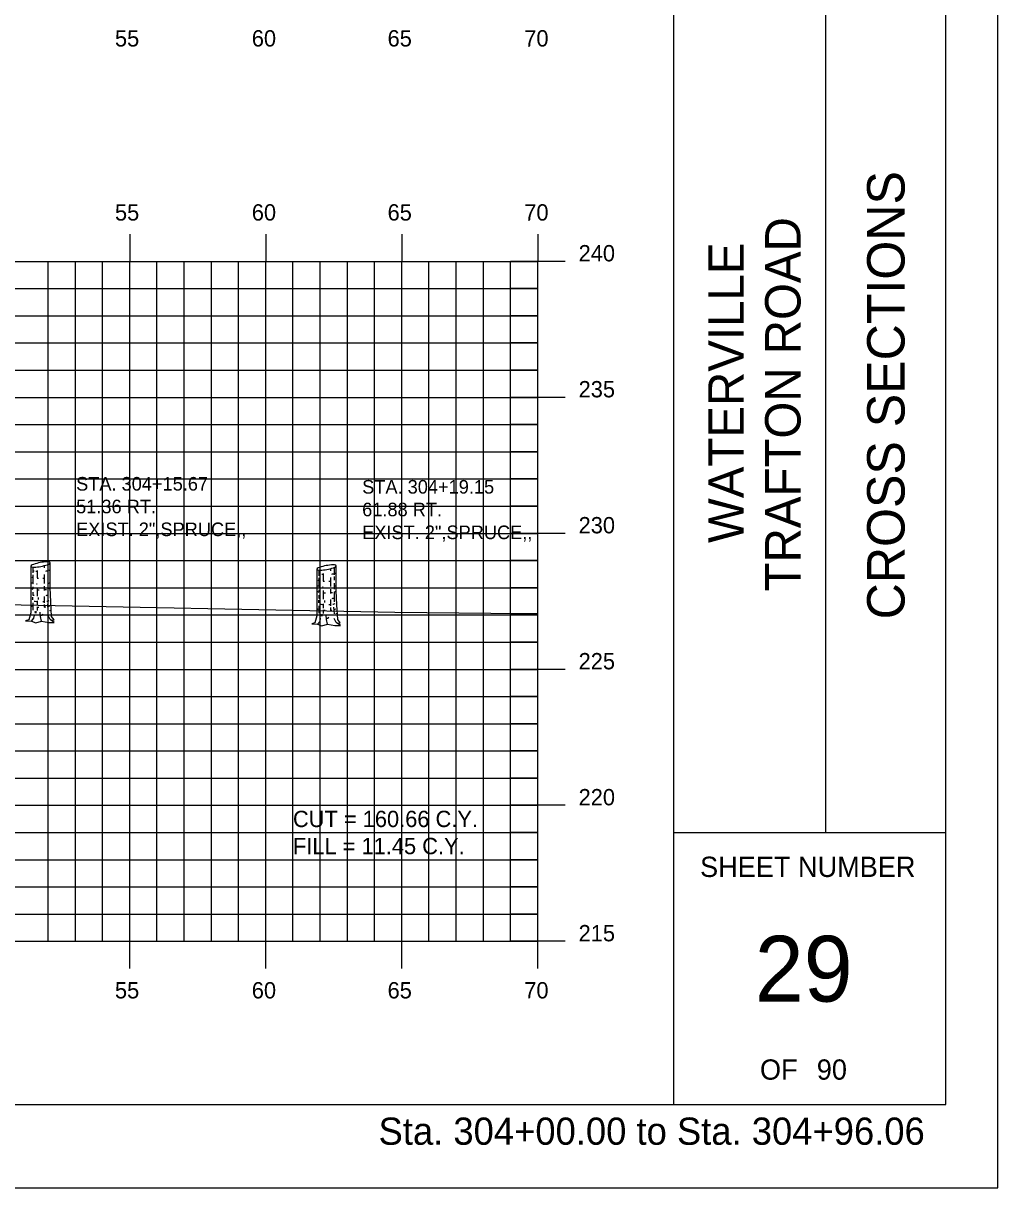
# Model space of a CAD drawing. Extents: x 1136989 to 1137159, y 608981 to 609091.
# Drawn here: x 1137123.23 to 1137159.05, y 608981.28 to 609024.09 of the extents above; entities that cross this region are included whole.
import ezdxf

# ---------------------------------------------------------------- set-up
doc = ezdxf.new("R2010")
doc.units = 0
for name, color, linetype in [('BORDER', 7, 'Continuous'), ('D_Text_Monospaced', 7, 'Continuous'), ('D_Text_Standard', 7, 'Continuous'), ('H_V ANNOTATION', 7, 'Continuous'), ('HIGHWAY_TITLE', 7, 'Continuous'), ('MAJOR', 7, 'Continuous'), ('MINOR', 7, 'Continuous'), ('PLOT BOUNDARY', 7, 'Continuous'), ('S_Roadway_Centerline', 7, 'Continuous'), ('S_Trees_Conifer_NonPay', 7, 'Continuous')]:
    doc.layers.add(name, color=color, linetype=linetype)

msp = doc.modelspace()

# ---------------------------------------------------------------- linework, layer by layer
at = {"layer": 'BORDER'}
for p, q in [((1137147.14, 608984.335), (1137147.14, 609089.335)), ((1137152.731, 608994.338), (1137152.731, 609029.338)), ((1137147.14, 608994.338), (1137157.14, 608994.338))]:
    msp.add_line(p, q, dxfattribs=at)
msp.add_lwpolyline([(1136997.14, 608984.335), (1137157.14, 608984.335), (1137157.14, 609089.335), (1136997.14, 609089.335)], close=True, dxfattribs=at)
at = {"layer": 'MAJOR'}
for p, q in [((1137127.14, 609016.337), (1137127.14, 609015.335)), ((1137132.14, 609016.337), (1137132.14, 609015.335)), ((1137137.14, 609016.337), (1137137.14, 609015.335)), ((1137142.14, 609016.337), (1137142.14, 609015.335)), ((1137002.14, 609015.335), (1137142.14, 609015.335)), ((1137002.14, 609015.335), (1137142.14, 609015.335)), ((1137127.14, 608990.335), (1137127.14, 609015.335)), ((1137132.14, 608990.335), (1137132.14, 609015.335)), ((1137137.14, 608990.335), (1137137.14, 609015.335)), ((1137143.142, 609015.335), (1137141.138, 609015.335)), ((1137142.14, 608990.335), (1137142.14, 609015.335)), ((1137142.14, 608990.335), (1137142.14, 609015.335)), ((1137002.14, 609010.335), (1137142.14, 609010.335)), ((1137143.142, 609010.335), (1137141.138, 609010.335)), ((1137002.14, 609005.335), (1137142.14, 609005.335)), ((1137143.142, 609005.335), (1137141.138, 609005.335)), ((1137002.14, 609000.335), (1137142.14, 609000.335)), ((1137143.142, 609000.335), (1137141.138, 609000.335)), ((1137002.14, 608995.335), (1137142.14, 608995.335)), ((1137143.142, 608995.335), (1137141.138, 608995.335)), ((1137002.14, 608990.335), (1137142.14, 608990.335)), ((1137002.14, 608990.335), (1137142.14, 608990.335)), ((1137127.14, 608989.333), (1137127.14, 608990.335)), ((1137132.14, 608989.333), (1137132.14, 608990.335)), ((1137137.14, 608989.333), (1137137.14, 608990.335)), ((1137143.142, 608990.335), (1137141.138, 608990.335)), ((1137142.14, 608989.333), (1137142.14, 608990.335))]:
    msp.add_line(p, q, dxfattribs=at)
at = {"layer": 'MINOR'}
for p, q in [((1137124.14, 608990.335), (1137124.14, 609015.335)), ((1137125.14, 608990.335), (1137125.14, 609015.335)), ((1137126.14, 608990.335), (1137126.14, 609015.335)), ((1137128.14, 608990.335), (1137128.14, 609015.335)), ((1137129.14, 608990.335), (1137129.14, 609015.335)), ((1137130.14, 608990.335), (1137130.14, 609015.335)), ((1137131.14, 608990.335), (1137131.14, 609015.335)), ((1137133.14, 608990.335), (1137133.14, 609015.335)), ((1137134.14, 608990.335), (1137134.14, 609015.335)), ((1137135.14, 608990.335), (1137135.14, 609015.335)), ((1137136.14, 608990.335), (1137136.14, 609015.335)), ((1137138.14, 608990.335), (1137138.14, 609015.335)), ((1137139.14, 608990.335), (1137139.14, 609015.335)), ((1137140.14, 608990.335), (1137140.14, 609015.335)), ((1137141.14, 608990.335), (1137141.14, 609015.335)), ((1137002.14, 609014.335), (1137142.14, 609014.335)), ((1137142.14, 609014.335), (1137141.138, 609014.335)), ((1137002.14, 609013.335), (1137142.14, 609013.335)), ((1137142.14, 609013.335), (1137141.138, 609013.335)), ((1137002.14, 609012.335), (1137142.14, 609012.335)), ((1137142.14, 609012.335), (1137141.138, 609012.335)), ((1137002.14, 609011.335), (1137142.14, 609011.335)), ((1137142.14, 609011.335), (1137141.138, 609011.335)), ((1137002.14, 609009.335), (1137142.14, 609009.335)), ((1137142.14, 609009.335), (1137141.138, 609009.335)), ((1137002.14, 609008.335), (1137142.14, 609008.335)), ((1137142.14, 609008.335), (1137141.138, 609008.335)), ((1137002.14, 609007.335), (1137142.14, 609007.335)), ((1137142.14, 609007.335), (1137141.138, 609007.335)), ((1137002.14, 609006.335), (1137142.14, 609006.335)), ((1137142.14, 609006.335), (1137141.138, 609006.335)), ((1137002.14, 609004.335), (1137142.14, 609004.335)), ((1137142.14, 609004.335), (1137141.138, 609004.335)), ((1137002.14, 609003.335), (1137142.14, 609003.335)), ((1137142.14, 609003.335), (1137141.138, 609003.335)), ((1137002.14, 609002.335), (1137142.14, 609002.335)), ((1137142.14, 609002.335), (1137141.138, 609002.335)), ((1137002.14, 609001.335), (1137142.14, 609001.335)), ((1137142.14, 609001.335), (1137141.138, 609001.335)), ((1137002.14, 608999.335), (1137142.14, 608999.335)), ((1137142.14, 608999.335), (1137141.138, 608999.335)), ((1137002.14, 608998.335), (1137142.14, 608998.335)), ((1137142.14, 608998.335), (1137141.138, 608998.335)), ((1137002.14, 608997.335), (1137142.14, 608997.335)), ((1137142.14, 608997.335), (1137141.138, 608997.335)), ((1137002.14, 608996.335), (1137142.14, 608996.335)), ((1137142.14, 608996.335), (1137141.138, 608996.335)), ((1137002.14, 608994.335), (1137142.14, 608994.335)), ((1137142.14, 608994.335), (1137141.138, 608994.335)), ((1137002.14, 608993.335), (1137142.14, 608993.335)), ((1137142.14, 608993.335), (1137141.138, 608993.335)), ((1137002.14, 608992.335), (1137142.14, 608992.335)), ((1137142.14, 608992.335), (1137141.138, 608992.335)), ((1137002.14, 608991.335), (1137142.14, 608991.335)), ((1137142.14, 608991.335), (1137141.138, 608991.335))]:
    msp.add_line(p, q, dxfattribs=at)
at = {"layer": 'PLOT BOUNDARY'}
msp.add_lwpolyline([(1136989.047, 608981.276), (1137159.047, 608981.276), (1137159.047, 609091.276), (1136989.047, 609091.276)], close=True, dxfattribs=at)
at = {"layer": 'S_Roadway_Centerline'}
msp.add_lwpolyline([(1137002.14, 609000.098), (1137009.532, 609000.178), (1137012.739, 609000.098), (1137016.466, 609000.152), (1137036.626, 609000.169), (1137038.714, 609000.163), (1137041.2, 609000.115), (1137042.648, 609000.935), (1137061.665, 609005.086), (1137063.035, 609005.338), (1137063.585, 609005.359), (1137073.925, 609005.86), (1137075.247, 609005.88), (1137084.732, 609006.033), (1137090.016, 609005.053), (1137090.597, 609004.926), (1137092.675, 609004.125), (1137094.237, 609003.522), (1137106.232, 609002.947), (1137113.452, 609002.818), (1137121.89, 609002.73), (1137136.879, 609002.44), (1137141.584, 609002.392), (1137142.14, 609002.4)], dxfattribs=at)
at = {"layer": 'S_Trees_Conifer_NonPay'}
for p, q in [((1137123.58, 609004.092), (1137123.58, 609003.887)), ((1137123.737, 609003.968), (1137123.737, 609003.694)), ((1137123.999, 609004.148), (1137123.999, 609004.069)), ((1137134.096, 609003.981), (1137134.096, 609003.776)), ((1137134.515, 609004.036), (1137134.515, 609003.958)), ((1137123.58, 609003.814), (1137123.58, 609003.483)), ((1137123.999, 609003.819), (1137123.999, 609003.494)), ((1137124.133, 609003.859), (1137124.133, 609003.728)), ((1137124.133, 609003.619), (1137124.133, 609003.393)), ((1137134.096, 609003.703), (1137134.096, 609003.372)), ((1137134.253, 609003.857), (1137134.253, 609003.583)), ((1137134.515, 609003.708), (1137134.515, 609003.383)), ((1137134.649, 609003.748), (1137134.649, 609003.617)), ((1137134.649, 609003.508), (1137134.649, 609003.282)), ((1137123.58, 609003.369), (1137123.58, 609003.29)), ((1137123.58, 609003.176), (1137123.58, 609003.066)), ((1137123.737, 609003.34), (1137123.737, 609003.022)), ((1137123.999, 609003.393), (1137123.999, 609003.239)), ((1137124.133, 609003.301), (1137124.133, 609002.925)), ((1137134.096, 609003.257), (1137134.096, 609003.179)), ((1137134.096, 609003.065), (1137134.096, 609002.955)), ((1137134.253, 609003.229), (1137134.253, 609002.911)), ((1137134.515, 609003.282), (1137134.515, 609003.128)), ((1137134.649, 609003.19), (1137134.649, 609002.814)), ((1137123.563, 609002.989), (1137123.563, 609002.892)), ((1137123.58, 609002.777), (1137123.58, 609002.51)), ((1137123.737, 609002.852), (1137123.737, 609002.693)), ((1137123.737, 609002.635), (1137123.737, 609002.504)), ((1137123.778, 609002.978), (1137123.778, 609002.908)), ((1137123.999, 609003.011), (1137123.999, 609002.777)), ((1137123.999, 609002.715), (1137123.999, 609002.629)), ((1137124.115, 609002.732), (1137124.132, 609002.487)), ((1137134.079, 609002.878), (1137134.079, 609002.78)), ((1137134.096, 609002.666), (1137134.096, 609002.399)), ((1137134.253, 609002.741), (1137134.253, 609002.582)), ((1137134.294, 609002.866), (1137134.294, 609002.797)), ((1137134.515, 609002.9), (1137134.515, 609002.666)), ((1137134.515, 609002.604), (1137134.515, 609002.518)), ((1137134.631, 609002.621), (1137134.648, 609002.376)), ((1137124.193, 609002.504), (1137124.254, 609002.51)), ((1137134.253, 609002.524), (1137134.253, 609002.393)), ((1137134.71, 609002.393), (1137134.77, 609002.399))]:
    msp.add_line(p, q, dxfattribs=at)
for points in [[(1137123.501, 609004.127), (1137123.501, 609002.409), (1137123.432, 609002.152), (1137123.312, 609002.118), (1137123.529, 609002.102), (1137123.688, 609002.043), (1137123.897, 609002.102), (1137124.16, 609002.054), (1137124.366, 609002.06), (1137124.214, 609002.163), (1137124.143, 609002.317)], [(1137124.133, 609004.188), (1137124.133, 609004.091), (1137124.133, 609003.926)], [(1137124.244, 609002.143), (1137124.36, 609002.152), (1137124.268, 609002.277), (1137124.235, 609002.818), (1137124.214, 609003.335), (1137124.214, 609004.254)], [(1137134.017, 609004.015), (1137134.017, 609002.297), (1137133.948, 609002.041), (1137133.828, 609002.007), (1137134.045, 609001.99), (1137134.204, 609001.932), (1137134.414, 609001.99), (1137134.676, 609001.943), (1137134.882, 609001.949), (1137134.731, 609002.052), (1137134.659, 609002.206)], [(1137134.649, 609004.077), (1137134.649, 609003.98), (1137134.649, 609003.815)], [(1137134.76, 609002.032), (1137134.876, 609002.041), (1137134.784, 609002.166), (1137134.751, 609002.707), (1137134.731, 609003.224), (1137134.731, 609004.143)], [(1137123.529, 609002.102), (1137123.619, 609002.214), (1137123.636, 609002.328)], [(1137123.66, 609002.464), (1137123.649, 609002.42), (1137123.699, 609002.409), (1137123.699, 609002.47)], [(1137123.897, 609002.102), (1137123.853, 609002.277), (1137123.847, 609002.442)], [(1137123.851, 609002.327), (1137123.92, 609002.322), (1137123.939, 609002.375)], [(1137134.045, 609001.99), (1137134.135, 609002.103), (1137134.152, 609002.217)], [(1137134.176, 609002.353), (1137134.165, 609002.309), (1137134.216, 609002.297), (1137134.216, 609002.359)], [(1137134.414, 609001.99), (1137134.369, 609002.166), (1137134.363, 609002.331)], [(1137134.367, 609002.216), (1137134.437, 609002.211), (1137134.455, 609002.263)]]:
    msp.add_lwpolyline(points, dxfattribs=at)
for centre, radius, start, end in [((1137123.52, 609004.126), 0.0186, 160.3798, 174.3267), ((1137123.515, 609004.127), 0.0141, 174.3267, 190.3798), ((1137123.515, 609004.127), 0.0141, 190.3798, 206.433), ((1137123.527, 609004.124), 0.0263, 141.6195, 160.3798), ((1137123.516, 609004.011), 0.0143, 180, 196.0515), ((1137123.519, 609004.129), 0.0186, 206.433, 220.3798), ((1137123.525, 609004.134), 0.0263, 220.3798, 239.1402), ((1137123.563, 609004.095), 0.0729, 130.3798, 141.6195), ((1137123.549, 609004.174), 0.0729, 239.1402, 250.3798), ((1137123.675, 609003.963), 0.245, 108.3946, 130.3798), ((1137123.607, 609004.336), 0.245, 250.3798, 272.3651), ((1137123.644, 609004.199), 0.245, 254.8461, 261.8968), ((1137124.174, 609002.464), 1.825, 100.3798, 108.3946), ((1137123.858, 609005.707), 1.767, 261.8968, 262.605), ((1137123.542, 609005.915), 1.825, 272.3651, 280.3798), ((1137123.858, 609005.707), 1.767, 264.3267, 266.0499), ((1137124.174, 609002.464), 1.825, 92.3651, 100.3798), ((1137123.542, 609005.915), 1.825, 280.3798, 288.3946), ((1137123.858, 609005.707), 1.767, 276.2449, 278.1032), ((1137124.109, 609004.043), 0.245, 70.3798, 92.3651), ((1137124.073, 609004.199), 0.245, 278.1032, 284.1859), ((1137124.04, 609004.415), 0.245, 288.3946, 310.3798), ((1137124.073, 609004.199), 0.245, 291.7653, 300), ((1137124.166, 609004.205), 0.0729, 59.1402, 70.3798), ((1137124.158, 609004.051), 0.0738, 300, 311.2506), ((1137124.152, 609004.284), 0.0729, 310.3798, 321.6195), ((1137124.19, 609004.245), 0.0263, 40.3798, 59.1402), ((1137124.189, 609004.016), 0.0267, 311.2506, 330), ((1137124.188, 609004.255), 0.0263, 321.6195, 340.3798), ((1137124.196, 609004.25), 0.0186, 26.433, 40.3798), ((1137124.196, 609004.012), 0.0189, 330, 343.9485), ((1137124.2, 609004.252), 0.0141, 10.3798, 26.433), ((1137124.196, 609004.253), 0.0186, 340.3798, 354.3267), ((1137124.2, 609004.252), 0.0141, 354.3267, 10.3798), ((1137134.036, 609004.015), 0.0186, 160.3798, 174.3267), ((1137134.031, 609004.015), 0.0141, 174.3267, 190.3798), ((1137134.043, 609004.012), 0.0263, 141.6195, 160.3798), ((1137134.031, 609004.015), 0.0141, 190.3798, 206.433), ((1137134.032, 609003.9), 0.0143, 180, 196.0515), ((1137134.035, 609004.017), 0.0186, 206.433, 220.3798), ((1137134.041, 609004.022), 0.0263, 220.3798, 239.1402), ((1137134.08, 609003.984), 0.0729, 130.3798, 141.6195), ((1137134.065, 609004.062), 0.0729, 239.1402, 250.3798), ((1137134.191, 609003.852), 0.245, 108.3946, 130.3798), ((1137134.123, 609004.225), 0.245, 250.3798, 272.3651), ((1137134.69, 609002.353), 1.825, 100.3798, 108.3946), ((1137134.058, 609005.804), 1.825, 272.3651, 280.3798), ((1137134.69, 609002.353), 1.825, 92.3651, 100.3798), ((1137134.058, 609005.804), 1.825, 280.3798, 288.3946), ((1137134.625, 609003.932), 0.245, 70.3798, 92.3651), ((1137134.556, 609004.304), 0.245, 288.3946, 310.3798), ((1137134.589, 609004.088), 0.245, 291.7653, 300), ((1137134.683, 609004.094), 0.0729, 59.1402, 70.3798), ((1137134.674, 609003.94), 0.0738, 300, 311.2506), ((1137134.668, 609004.173), 0.0729, 310.3798, 321.6195), ((1137134.706, 609004.134), 0.0263, 40.3798, 59.1402), ((1137134.705, 609003.905), 0.0267, 311.2506, 330), ((1137134.705, 609004.144), 0.0263, 321.6195, 340.3798), ((1137134.712, 609004.139), 0.0186, 26.433, 40.3798), ((1137134.716, 609004.141), 0.0141, 10.3798, 26.433), ((1137134.712, 609004.141), 0.0186, 340.3798, 354.3267), ((1137134.712, 609003.901), 0.0189, 330, 343.9485), ((1137134.716, 609004.141), 0.0141, 354.3267, 10.3798), ((1137123.516, 609003.545), 0.0143, 180, 196.0515), ((1137123.52, 609003.546), 0.0189, 196.0515, 210), ((1137123.527, 609003.55), 0.0267, 210, 228.7494), ((1137123.558, 609003.585), 0.0738, 228.7494, 240), ((1137123.644, 609003.733), 0.245, 240, 246.7914), ((1137123.645, 609003.947), 0.245, 244.3148, 257.5375), ((1137123.644, 609003.733), 0.245, 254.8461, 257.5454), ((1137123.858, 609005.241), 1.767, 265.2285, 266.1325), ((1137123.86, 609005.455), 1.767, 265.8991, 267.5962), ((1137123.86, 609005.455), 1.767, 272.7221, 274.4847), ((1137124.073, 609003.733), 0.245, 284.1859, 300), ((1137124.158, 609003.585), 0.0738, 300, 311.2506), ((1137124.189, 609003.55), 0.0267, 311.2506, 330), ((1137124.191, 609003.764), 0.0267, 311.2506, 330), ((1137124.196, 609003.546), 0.0189, 330, 343.9485), ((1137124.198, 609003.76), 0.0189, 330, 343.9485), ((1137134.162, 609003.836), 0.245, 244.3148, 257.5375), ((1137134.16, 609004.088), 0.245, 254.8461, 261.8968), ((1137134.374, 609005.596), 1.767, 261.8968, 262.605), ((1137134.374, 609005.596), 1.767, 264.3267, 266.0499), ((1137134.376, 609005.343), 1.767, 265.8991, 267.5962), ((1137134.376, 609005.343), 1.767, 272.7221, 274.4847), ((1137134.374, 609005.596), 1.767, 276.2449, 278.1032), ((1137134.589, 609004.088), 0.245, 278.1032, 284.1859), ((1137134.707, 609003.653), 0.0267, 311.2506, 330), ((1137134.714, 609003.649), 0.0189, 330, 343.9485), ((1137123.516, 609003.333), 0.0143, 180, 196.0515), ((1137123.521, 609003.335), 0.0189, 196.0515, 210), ((1137123.527, 609003.339), 0.0267, 210, 228.7494), ((1137123.558, 609003.374), 0.0738, 228.7494, 240), ((1137123.644, 609003.522), 0.245, 240, 254.9514), ((1137123.643, 609003.303), 0.245, 254.9814, 261.8968), ((1137123.858, 609004.81), 1.767, 261.8968, 262.45), ((1137123.858, 609005.029), 1.767, 266.0429, 268.5525), ((1137123.858, 609005.029), 1.767, 274.5361, 277.0026), ((1137123.858, 609004.81), 1.767, 276.7966, 278.1032), ((1137124.072, 609003.303), 0.245, 278.1032, 284.3207), ((1137124.073, 609003.522), 0.245, 292.1924, 300), ((1137124.158, 609003.374), 0.0738, 300, 311.2506), ((1137124.19, 609003.339), 0.0267, 311.2506, 330), ((1137124.196, 609003.335), 0.0189, 330, 343.9485), ((1137134.032, 609003.434), 0.0143, 180, 196.0515), ((1137134.037, 609003.435), 0.0189, 196.0515, 210), ((1137134.032, 609003.222), 0.0143, 180, 196.0515), ((1137134.037, 609003.224), 0.0189, 196.0515, 210), ((1137134.043, 609003.439), 0.0267, 210, 228.7494), ((1137134.044, 609003.227), 0.0267, 210, 228.7494), ((1137134.074, 609003.474), 0.0738, 228.7494, 240), ((1137134.075, 609003.263), 0.0738, 228.7494, 240), ((1137134.16, 609003.622), 0.245, 240, 246.7914), ((1137134.16, 609003.411), 0.245, 240, 254.9514), ((1137134.16, 609003.622), 0.245, 254.8461, 257.5454), ((1137134.374, 609005.13), 1.767, 265.2285, 266.1325), ((1137134.375, 609004.918), 1.767, 266.0429, 268.5525), ((1137134.375, 609004.918), 1.767, 274.5361, 277.0026), ((1137134.589, 609003.622), 0.245, 284.1859, 300), ((1137134.589, 609003.411), 0.245, 292.1924, 300), ((1137134.674, 609003.474), 0.0738, 300, 311.2506), ((1137134.675, 609003.263), 0.0738, 300, 311.2506), ((1137134.705, 609003.439), 0.0267, 311.2506, 330), ((1137134.706, 609003.227), 0.0267, 311.2506, 330), ((1137134.712, 609003.435), 0.0189, 330, 343.9485), ((1137134.712, 609003.224), 0.0189, 330, 343.9485), ((1137123.515, 609002.897), 0.0143, 180, 196.0515), ((1137123.515, 609002.691), 0.0143, 180, 196.0515), ((1137123.519, 609002.693), 0.0189, 196.0515, 210), ((1137123.526, 609002.696), 0.0267, 210, 228.7494), ((1137123.557, 609002.732), 0.0738, 228.7494, 240), ((1137123.642, 609002.88), 0.245, 240, 249.1675), ((1137123.858, 609004.593), 1.767, 262.2622, 265.0496), ((1137123.857, 609004.387), 1.767, 266.0862, 268.2187), ((1137123.858, 609004.593), 1.767, 272.6293, 274.5612), ((1137123.857, 609004.387), 1.767, 274.2776, 276.3006), ((1137123.858, 609004.593), 1.767, 277.63, 278.1032), ((1137124.072, 609003.085), 0.245, 278.1032, 294.6056), ((1137124.072, 609002.88), 0.245, 284.0684, 300), ((1137124.157, 609002.732), 0.0738, 300, 302.05), ((1137134.032, 609002.786), 0.0143, 180, 196.0515), ((1137134.159, 609003.191), 0.245, 254.9814, 261.8968), ((1137134.374, 609004.699), 1.767, 261.8968, 262.45), ((1137134.374, 609004.482), 1.767, 262.2622, 265.0496), ((1137134.374, 609004.482), 1.767, 272.6293, 274.5612), ((1137134.374, 609004.699), 1.767, 276.7966, 278.1032), ((1137134.374, 609004.482), 1.767, 277.63, 278.1032), ((1137134.589, 609003.191), 0.245, 278.1032, 284.3207), ((1137134.589, 609002.974), 0.245, 278.1032, 294.6056), ((1137134.031, 609002.58), 0.0143, 180, 196.0515), ((1137134.035, 609002.581), 0.0189, 196.0515, 210), ((1137134.042, 609002.585), 0.0267, 210, 228.7494), ((1137134.073, 609002.621), 0.0738, 228.7494, 240), ((1137134.159, 609002.769), 0.245, 240, 249.1675), ((1137134.373, 609004.276), 1.767, 266.0862, 268.2187), ((1137134.373, 609004.276), 1.767, 274.2776, 276.3006), ((1137134.588, 609002.769), 0.245, 284.0684, 300), ((1137134.673, 609002.621), 0.0738, 300, 302.05)]:
    msp.add_arc(centre, radius, start, end, dxfattribs=at)

# ---------------------------------------------------------------- texts
at = {"layer": 'BORDER'}
msp.add_text('CROSS SECTIONS', height=1.37787, rotation=90, dxfattribs=at).set_placement((1137155.624, 609002.172))
for s, height, p in [('SHEET NUMBER', 0.74527, (1137148.105, 608992.701)), ('29', 2.4194, (1137150.116, 608988.118)), ('OF', 0.7453, (1137150.307, 608985.248)), ('90', 0.7453, (1137152.396, 608985.248))]:
    msp.add_text(s, height=height, dxfattribs=at).set_placement(p)
at = {"layer": 'D_Text_Monospaced'}
for s, height, p in [('STA. 304+15.67', 0.49998, (1137125.168, 609006.907)), ('STA. 304+19.15', 0.49998, (1137135.684, 609006.796)), ('51.36 RT.', 0.5, (1137125.168, 609006.073)), ('61.88 RT.', 0.5, (1137135.684, 609005.962)), ('EXIST. 2",SPRUCE,,', 0.49998, (1137125.168, 609005.233)), ('EXIST. 2",SPRUCE,,', 0.49998, (1137135.684, 609005.122))]:
    msp.add_text(s, height=height, dxfattribs=at).set_placement(p)
at = {"layer": 'D_Text_Standard'}
for s, p in [('CUT = 160.66 C.Y.', (1137133.14, 608994.535)), ('FILL = 11.45 C.Y.', (1137133.14, 608993.539))]:
    msp.add_text(s, height=0.6, dxfattribs=at).set_placement(p)
at = {"layer": 'H_V ANNOTATION'}
for s, height, p in [('55', 0.6, (1137126.596, 609023.235)), ('60', 0.6, (1137131.626, 609023.235)), ('65', 0.6, (1137136.618, 609023.235)), ('70', 0.6, (1137141.642, 609023.235)), ('55', 0.6, (1137126.596, 609016.835)), ('60', 0.6, (1137131.626, 609016.835)), ('65', 0.6, (1137136.618, 609016.835)), ('70', 0.6, (1137141.642, 609016.835)), ('240', 0.6, (1137143.64, 609015.335)), ('235', 0.6, (1137143.64, 609010.335)), ('230', 0.6, (1137143.64, 609005.335)), ('225', 0.6, (1137143.64, 609000.335)), ('220', 0.6, (1137143.64, 608995.335)), ('215', 0.6, (1137143.64, 608990.335)), ('55', 0.6, (1137126.596, 608988.235)), ('60', 0.6, (1137131.626, 608988.235)), ('65', 0.6, (1137136.618, 608988.235)), ('70', 0.6, (1137141.642, 608988.235)), ('Sta. 304+00.00 to Sta. 304+96.06', 1.0002, (1137136.286, 608982.855))]:
    msp.add_text(s, height=height, dxfattribs=at).set_placement(p)
at = {"layer": 'HIGHWAY_TITLE'}
for s, height, p in [('TRAFTON ROAD', 1.30428, (1137151.799, 609003.201)), ('WATERVILLE', 1.3043, (1137149.712, 609004.98))]:
    msp.add_text(s, height=height, rotation=90, dxfattribs=at).set_placement(p)

doc.saveas('drawing.dxf')
